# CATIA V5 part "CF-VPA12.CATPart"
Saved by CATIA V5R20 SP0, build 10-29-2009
Part number: CF-VPA12
Bounding box of the stored display mesh (mm): x 0 to 31, y -6 to 6, z -6 to 6
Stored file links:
  C:\Users\Utente\Desktop\IO LAVORO\3D X SITO CF\X SITO\PLASTICA\CF-VPA\CF-VPA12.CATPart
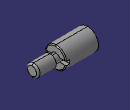
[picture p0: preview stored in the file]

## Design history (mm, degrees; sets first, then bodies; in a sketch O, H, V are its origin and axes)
Set1
  DatumSurface1 to DatumSurface30 "CF-VPA12"
Body1 (main body)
